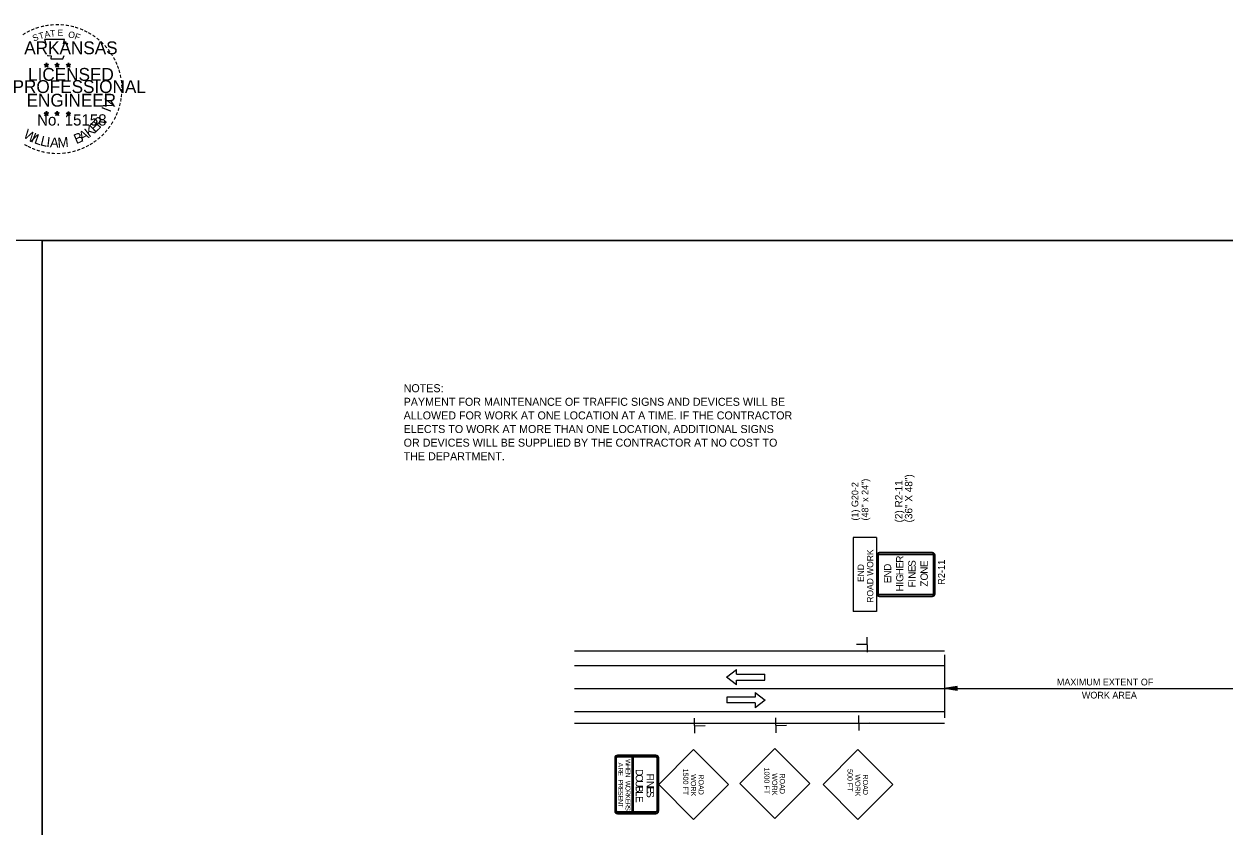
# Model space of a CAD drawing. Extents: x 32485 to 39285, y 55121 to 58033.
# Drawn here: x 37571 to 38508, y 57407 to 58033 of the extents above; entities that cross this region are included whole.
import ezdxf

# ---------------------------------------------------------------- set-up
doc = ezdxf.new("R2010")
doc.units = 0
for name, color, linetype in [('Default', 7, 'Continuous'), ('DSN_DRFT_Junk-No-Plot', 7, 'Continuous'), ('R_Border', 7, 'Continuous'), ('R_Border Notes', 7, 'Continuous'), ('R_Dimension', 7, 'Continuous'), ('R_Draft', 7, 'Continuous'), ('R_Exist Surface', 7, 'Continuous')]:
    doc.layers.add(name, color=color, linetype=linetype)

msp = doc.modelspace()

# ---------------------------------------------------------------- linework, layer by layer
at = {"layer": 'Default'}
for p, q in [((38236.12, 57618.46), (38236.12, 57588.47)), ((38236.71, 57618.46), (38236.71, 57588.47)), ((38237.54, 57588.47), (38237.54, 57618.46)), ((38279.66, 57620.6), (38238.26, 57620.6)), ((38279.66, 57620), (38238.26, 57620)), ((38238.26, 57619.17), (38279.66, 57619.17)), ((38280.37, 57618.46), (38280.37, 57588.47)), ((38281.21, 57588.47), (38281.21, 57618.46)), ((38281.8, 57588.47), (38281.8, 57618.46)), ((38279.66, 57587.76), (38238.26, 57587.76)), ((38238.26, 57586.93), (38279.66, 57586.93)), ((38238.26, 57586.33), (38279.66, 57586.33)), ((38289.12, 57540.69), (38289.12, 57491.65)), ((38119.1, 57523.38), (38126.88, 57529.38)), ((38126.88, 57517.38), (38119.1, 57523.38)), ((38126.88, 57525.63), (38126.88, 57529.38)), ((38126.88, 57525.63), (38148.95, 57525.63)), ((38126.88, 57521.13), (38148.95, 57521.13)), ((38126.88, 57517.38), (38126.88, 57521.13)), ((38148.95, 57521.13), (38148.95, 57525.63)), ((38141.33, 57511.53), (38141.33, 57507.78)), ((38141.33, 57511.53), (38149.11, 57505.53)), ((38289.12, 57514.51), (38546.87, 57514.51)), ((38345.15, 57514.51), (38490.85, 57514.51)), ((38141.33, 57507.78), (38119.26, 57507.78)), ((38119.26, 57507.78), (38119.26, 57503.28)), ((38141.33, 57503.28), (38119.26, 57503.28)), ((38149.11, 57505.53), (38141.33, 57499.53)), ((38141.33, 57503.28), (38141.33, 57499.53)), ((38031.84, 57460.42), (38031.84, 57419.02)), ((38032.43, 57460.42), (38032.43, 57419.02)), ((38033.26, 57419.02), (38033.26, 57460.42)), ((38063.96, 57462.57), (38033.98, 57462.57)), ((38063.96, 57461.97), (38033.98, 57461.97)), ((38033.98, 57461.14), (38063.96, 57461.14)), ((38045.46, 57418.31), (38045.46, 57461.14)), ((38045.46, 57461.14), (38046.29, 57461.14)), ((38046.29, 57461.14), (38046.29, 57418.31)), ((38064.67, 57460.42), (38064.67, 57419.02)), ((38065.5, 57419.02), (38065.5, 57460.42)), ((38066.1, 57419.02), (38066.1, 57460.42)), ((38063.96, 57418.31), (38033.98, 57418.31)), ((38033.98, 57417.48), (38063.96, 57417.48)), ((38046.29, 57418.31), (38045.46, 57418.31)), ((38033.98, 57416.88), (38063.96, 57416.88))]:
    msp.add_line(p, q, dxfattribs=at)
for points in [[(35885, 57863.91), (35885, 56763.91), (37585, 56763.91), (37585, 57863.91)], [(37585, 57863.91), (37585, 56763.91), (39285, 56763.91), (39285, 57863.91)]]:
    msp.add_lwpolyline(points, close=True, dxfattribs=at)
for centre, radius, start, end in [((38238.26, 57618.46), 2.14, 90, 180), ((38238.26, 57618.46), 1.55, 90, 180), ((38238.26, 57618.46), 0.714, 90, 180), ((38279.66, 57618.46), 2.14, 0.00001, 90.00001), ((38279.66, 57618.46), 1.55, 0, 90.00001), ((38279.66, 57618.46), 0.714, 0, 90.00001), ((38238.26, 57588.47), 2.14, 180, 270), ((38238.26, 57588.47), 1.55, 180, 270.00001), ((38238.26, 57588.47), 0.714, 180, 270.00001), ((38279.66, 57588.47), 2.14, 270, 0.00001), ((38279.66, 57588.47), 1.55, 270.00001, 0), ((38279.66, 57588.47), 0.714, 270.00001, 0), ((38033.98, 57460.42), 2.14, 90, 180.00001), ((38033.98, 57460.42), 1.55, 90.00001, 180), ((38033.98, 57460.42), 0.714, 90.00001, 180), ((38063.96, 57460.42), 2.14, 0, 90), ((38063.96, 57460.42), 1.55, 0, 90.00001), ((38063.96, 57460.42), 0.714, 0, 90.00001), ((38033.98, 57419.02), 2.14, 180.00001, 270.00001), ((38033.98, 57419.02), 1.55, 180, 270.00001), ((38033.98, 57419.02), 0.714, 180, 270.00001), ((38063.96, 57419.02), 2.14, 270, 0), ((38063.96, 57419.02), 1.55, 270, 0), ((38063.96, 57419.02), 0.714, 270, 0)]:
    msp.add_arc(centre, radius, start, end, dxfattribs=at)
at = {"layer": 'DSN_DRFT_Junk-No-Plot'}
msp.add_lwpolyline([(37585, 57863.91), (39285, 57863.91), (39285, 56763.91), (37585, 56763.91)], close=True, dxfattribs=at)
at = {"layer": 'R_Border'}
for p, q in [((38217.92, 57632.43), (38217.92, 57574.5)), ((38236.12, 57632.43), (38217.92, 57632.43)), ((38236.12, 57632.43), (38236.12, 57574.5)), ((38236.12, 57574.5), (38217.92, 57574.5)), ((38228.51, 57548.79), (38220.46, 57548.76)), ((38228.65, 57554.66), (38228.7, 57542.88)), ((38222.53, 57481.76), (38222.33, 57493.54)), ((38094.2, 57479.6), (38093.99, 57491.38)), ((38094.26, 57485.47), (38102.31, 57485.6)), ((38157.84, 57479.9), (38157.64, 57491.67)), ((38157.91, 57485.76), (38165.95, 57485.89)), ((38222.6, 57487.63), (38230.64, 57487.76)), ((38066.1, 57439.72), (38093.36, 57467)), ((38120.64, 57439.72), (38093.36, 57467)), ((38129.45, 57440.42), (38156.71, 57467.7)), ((38183.99, 57440.42), (38156.71, 57467.7)), ((38194.35, 57439.63), (38221.61, 57466.91)), ((38248.89, 57439.63), (38221.61, 57466.91)), ((38093.36, 57412.44), (38066.1, 57439.72)), ((38093.36, 57412.44), (38120.64, 57439.72)), ((38156.71, 57413.14), (38129.45, 57440.42)), ((38156.71, 57413.14), (38183.99, 57440.42)), ((38221.61, 57412.35), (38194.35, 57439.63)), ((38221.61, 57412.35), (38248.89, 57439.63))]:
    msp.add_line(p, q, dxfattribs=at)
at = {"layer": 'R_Border Notes'}
msp.add_lwpolyline([(35885, 56763.91), (37585, 56763.91), (37585, 57863.91), (35885, 57863.91)], close=True, dxfattribs=at)
at = {"layer": 'R_Dimension'}
for p, q in [((37586.59, 58001.4), (37588.33, 58000.85)), ((37586.59, 58001.4), (37587.85, 58001.18)), ((37586.59, 58001.4), (37587.77, 58000.79)), ((37587.25, 57999.36), (37588.33, 58000.85)), ((37587.25, 57999.36), (37587.88, 58000.58)), ((37587.25, 57999.36), (37588.32, 58000.45)), ((37588.33, 58002.67), (37588.13, 58001.41)), ((37589.4, 57999.36), (37588.32, 58000.43)), ((37588.33, 58000.85), (37588.33, 58002.67)), ((37588.33, 58002.67), (37588.58, 58001.42)), ((37590.07, 58001.4), (37588.33, 58000.85)), ((37589.4, 57999.36), (37588.33, 58000.85)), ((37590.07, 58001.4), (37588.64, 58001.16)), ((37589.4, 57999.36), (37588.71, 58000.82)), ((37590.07, 58001.4), (37589.05, 58000.89)), ((37594.94, 58001.4), (37596.68, 58000.85)), ((37594.94, 58001.4), (37596.2, 58001.18)), ((37594.94, 58001.4), (37596.12, 58000.79)), ((37595.6, 57999.36), (37596.68, 58000.85)), ((37595.6, 57999.36), (37596.23, 58000.58)), ((37595.6, 57999.36), (37596.67, 58000.45)), ((37596.68, 58002.67), (37596.48, 58001.41)), ((37597.75, 57999.36), (37596.67, 58000.43)), ((37596.68, 58000.85), (37596.68, 58002.67)), ((37596.68, 58002.67), (37596.93, 58001.42)), ((37598.42, 58001.4), (37596.68, 58000.85)), ((37597.75, 57999.36), (37596.68, 58000.85)), ((37598.42, 58001.4), (37596.99, 58001.16)), ((37597.75, 57999.36), (37597.06, 58000.82)), ((37598.42, 58001.4), (37597.4, 58000.89)), ((37603.76, 58001.34), (37605.5, 58000.79)), ((37603.76, 58001.34), (37605.02, 58001.12)), ((37603.76, 58001.34), (37604.94, 58000.73)), ((37604.42, 57999.3), (37605.5, 58000.79)), ((37604.42, 57999.3), (37605.05, 58000.52)), ((37604.42, 57999.3), (37605.49, 58000.39)), ((37605.5, 58002.61), (37605.3, 58001.35)), ((37606.57, 57999.3), (37605.49, 58000.37)), ((37605.5, 58000.79), (37605.5, 58002.61)), ((37605.5, 58002.61), (37605.75, 58001.36)), ((37607.24, 58001.34), (37605.5, 58000.79)), ((37606.57, 57999.3), (37605.5, 58000.79)), ((37607.24, 58001.34), (37605.81, 58001.1)), ((37606.57, 57999.3), (37605.88, 58000.76)), ((37607.24, 58001.34), (37606.22, 58000.83)), ((37586.57, 57963.54), (37588.31, 57962.98)), ((37586.57, 57963.54), (37587.83, 57963.31)), ((37586.57, 57963.54), (37587.75, 57962.93)), ((37587.23, 57961.5), (37588.31, 57962.98)), ((37587.23, 57961.5), (37587.86, 57962.72)), ((37587.23, 57961.5), (37588.3, 57962.58)), ((37588.31, 57964.81), (37588.11, 57963.55)), ((37589.38, 57961.5), (37588.3, 57962.57)), ((37588.31, 57962.98), (37588.31, 57964.81)), ((37588.31, 57964.81), (37588.56, 57963.56)), ((37590.05, 57963.54), (37588.31, 57962.98)), ((37589.38, 57961.5), (37588.31, 57962.98)), ((37590.05, 57963.54), (37588.62, 57963.29)), ((37589.38, 57961.5), (37588.69, 57962.95)), ((37590.05, 57963.54), (37589.03, 57963.03)), ((37594.91, 57963.54), (37596.66, 57962.98)), ((37594.91, 57963.54), (37596.18, 57963.31)), ((37594.91, 57963.54), (37596.1, 57962.93)), ((37595.58, 57961.5), (37596.66, 57962.98)), ((37595.58, 57961.5), (37596.21, 57962.72)), ((37595.58, 57961.5), (37596.65, 57962.58)), ((37596.66, 57964.81), (37596.45, 57963.55)), ((37597.72, 57961.5), (37596.65, 57962.57)), ((37596.66, 57962.98), (37596.66, 57964.81)), ((37596.66, 57964.81), (37596.9, 57963.56)), ((37598.39, 57963.54), (37596.66, 57962.98)), ((37597.72, 57961.5), (37596.66, 57962.98)), ((37598.39, 57963.54), (37596.96, 57963.29)), ((37597.72, 57961.5), (37597.04, 57962.95)), ((37598.39, 57963.54), (37597.37, 57963.03)), ((37603.75, 57963.49), (37605.49, 57962.93)), ((37603.75, 57963.49), (37605.01, 57963.26)), ((37603.75, 57963.49), (37604.93, 57962.88)), ((37604.41, 57961.45), (37605.49, 57962.93)), ((37604.41, 57961.45), (37605.04, 57962.67)), ((37604.41, 57961.45), (37605.48, 57962.53)), ((37605.49, 57964.76), (37605.29, 57963.5)), ((37606.56, 57961.45), (37605.48, 57962.52)), ((37605.49, 57962.93), (37605.49, 57964.76)), ((37605.49, 57964.76), (37605.74, 57963.51)), ((37607.23, 57963.49), (37605.49, 57962.93)), ((37606.56, 57961.45), (37605.49, 57962.93)), ((37607.23, 57963.49), (37605.8, 57963.24)), ((37606.56, 57961.45), (37605.87, 57962.9)), ((37607.23, 57963.49), (37606.21, 57962.98))]:
    msp.add_line(p, q, dxfattribs=at)
for points in [[(37586.79, 58020.79), (37588.14, 58016.66)], [(37604.35, 58016.18), (37605.06, 58017.6), (37601.63, 58017.48), (37602.37, 58020.79), (37586.79, 58020.79)], [(37589.25, 58008.68), (37589.25, 58008.24), (37592.07, 58008.15), (37591.8, 58005.78), (37601.15, 58005.78), (37602.15, 58008.46)], [(37588.33, 58002.67), (37589.4, 57999.36), (37586.59, 58001.4), (37590.07, 58001.4), (37587.25, 57999.36), (37588.33, 58002.67)], [(37596.68, 58002.67), (37597.75, 57999.36), (37594.94, 58001.4), (37598.42, 58001.4), (37595.6, 57999.36), (37596.68, 58002.67)], [(37605.5, 58002.61), (37606.57, 57999.3), (37603.76, 58001.34), (37607.24, 58001.34), (37604.42, 57999.3), (37605.5, 58002.61)], [(37588.31, 57964.81), (37589.38, 57961.5), (37586.57, 57963.54), (37590.05, 57963.54), (37587.23, 57961.5), (37588.31, 57964.81)], [(37596.66, 57964.81), (37597.72, 57961.5), (37594.91, 57963.54), (37598.39, 57963.54), (37595.58, 57961.5), (37596.66, 57964.81)], [(37605.49, 57964.76), (37606.56, 57961.45), (37603.75, 57963.49), (37607.23, 57963.49), (37604.41, 57961.45), (37605.49, 57964.76)]]:
    msp.add_lwpolyline(points, dxfattribs=at)
for centre, radius in [((37588.33, 58000.84), 0.861), ((37588.33, 58000.84), 0.723), ((37588.33, 58000.84), 0.579), ((37588.33, 58000.84), 0.495), ((37588.33, 58000.84), 0.374), ((37588.33, 58000.84), 0.248), ((37588.33, 58000.84), 0.148), ((37596.68, 58000.84), 0.861), ((37596.68, 58000.84), 0.723), ((37596.68, 58000.84), 0.579), ((37596.68, 58000.84), 0.495), ((37596.68, 58000.84), 0.374), ((37596.68, 58000.84), 0.248), ((37596.68, 58000.84), 0.148), ((37605.5, 58000.78), 0.861), ((37605.5, 58000.78), 0.723), ((37605.5, 58000.78), 0.579), ((37605.5, 58000.78), 0.495), ((37605.5, 58000.78), 0.374), ((37605.5, 58000.78), 0.248), ((37605.5, 58000.78), 0.148), ((37588.31, 57962.98), 0.861), ((37588.31, 57962.98), 0.723), ((37588.31, 57962.98), 0.579), ((37588.31, 57962.98), 0.495), ((37588.31, 57962.98), 0.374), ((37588.31, 57962.98), 0.248), ((37588.31, 57962.98), 0.148), ((37596.65, 57962.98), 0.861), ((37596.65, 57962.98), 0.723), ((37596.65, 57962.98), 0.579), ((37596.65, 57962.98), 0.495), ((37596.65, 57962.98), 0.374), ((37596.65, 57962.98), 0.248), ((37596.65, 57962.98), 0.148), ((37605.49, 57962.93), 0.861), ((37605.49, 57962.93), 0.723), ((37605.49, 57962.93), 0.579), ((37605.49, 57962.93), 0.495), ((37605.49, 57962.93), 0.374), ((37605.49, 57962.93), 0.248), ((37605.49, 57962.93), 0.148)]:
    msp.add_circle(centre, radius, dxfattribs=at)
at = {"layer": 'R_Draft'}
for p, q in [((38299.12, 57516.01), (38289.12, 57514.51)), ((38299.12, 57513.01), (38289.12, 57514.51)), ((38299.12, 57515.76), (38290.79, 57514.51)), ((38299.12, 57513.26), (38290.79, 57514.51)), ((38299.12, 57515.5), (38292.51, 57514.51)), ((38299.12, 57513.51), (38292.51, 57514.51)), ((38299.12, 57515.25), (38294.18, 57514.51)), ((38299.12, 57513.76), (38294.18, 57514.51)), ((38299.12, 57515), (38295.87, 57514.51)), ((38299.12, 57514.02), (38295.87, 57514.51)), ((38299.12, 57514.74), (38297.54, 57514.51)), ((38299.12, 57514.27), (38297.54, 57514.51)), ((38299.12, 57513.01), (38299.12, 57516.01))]:
    msp.add_line(p, q, dxfattribs=at)
at = {"layer": 'R_Exist Surface'}
for p, q in [((38000.34, 57544.01), (38289.12, 57544.01)), ((38000.34, 57532.51), (38289.12, 57532.51)), ((38000.34, 57514.51), (38289.12, 57514.51)), ((38000.34, 57496.51), (38289.12, 57496.51)), ((38000.34, 57487.51), (38289.12, 57487.51))]:
    msp.add_line(p, q, dxfattribs=at)

# ---------------------------------------------------------------- texts
at = {"layer": 'Default'}
for s, height, p in [('NOTES: ', 6.25, (37867.1, 57745.7)), ('PAYMENT FOR MAINTENANCE OF TRAFFIC SIGNS AND DEVICES WILL BE ', 6.25, (37867.1, 57735.08)), ('ALLOWED FOR WORK AT ONE LOCATION AT A TIME. IF THE CONTRACTOR', 6.25, (37867.1, 57724.46)), ('ELECTS TO WORK AT MORE THAN ONE LOCATION, ADDITIONAL SIGNS', 6.25, (37867.1, 57713.83)), ('OR DEVICES WILL BE SUPPLIED BY THE CONTRACTOR AT NO COST TO ', 6.25, (37867.1, 57703.21)), ('THE DEPARTMENT.', 6.25, (37867.1, 57692.58)), ('MAXIMUM EXTENT OF ', 5.25, (38376.8, 57516.94)), ('WORK AREA', 5.25, (38396.32, 57506.75))]:
    msp.add_text(s, height=height, dxfattribs=at).set_placement(p)
for s, height, rotation, p in [('R', 5.71, 90, (38257.06, 57612.7)), ('S', 5.71, 90, (38266.57, 57609.55)), ('R2-11', 5.384, 90, (38289.42, 57595.41)), ('D', 5.71, 90, (38247.54, 57606.41)), ('N', 5.71, 90, (38247.54, 57601.15)), ('E', 5.71, 90, (38257.06, 57608.18)), ('H', 5.71, 90, (38257.06, 57602.92)), ('E', 5.71, 90, (38266.57, 57605.44)), ('N', 5.71, 90, (38266.57, 57600.18)), ('E', 5.71, 90, (38276.09, 57609.35)), ('N', 5.71, 90, (38276.09, 57604.09)), ('E', 5.71, 90, (38247.54, 57596.64)), ('G', 5.71, 90, (38257.06, 57597.78)), ('I', 5.71, 90, (38257.06, 57595.61)), ('I', 5.71, 90, (38266.57, 57597.89)), ('F', 5.71, 90, (38266.57, 57593.49)), ('O', 5.71, 90, (38276.09, 57598.78)), ('Z', 5.71, 90, (38276.09, 57594.04)), ('H', 5.71, 90, (38257.06, 57590.35)), ('A', 3.81, 270, (38034.51, 57456.78)), ('W', 3.81, 270, (38040.22, 57459.42)), ('H', 3.81, 270, (38040.22, 57455.46)), ('R', 3.81, 270, (38034.51, 57452.97)), ('E', 3.81, 270, (38034.51, 57449.74)), ('E', 3.81, 270, (38040.22, 57451.96)), ('N', 3.81, 270, (38040.22, 57448.95)), ('O', 5.71, 270, (38048.19, 57447.49)), ('D', 5.71, 270, (38048.19, 57451.72)), ('F', 5.71, 270, (38056.76, 57448.23)), ('P', 3.81, 270, (38034.51, 57443.57)), ('R', 3.81, 270, (38034.51, 57440.41)), ('E', 3.81, 270, (38034.51, 57437.17)), ('O', 3.81, 270, (38040.22, 57438.68)), ('W', 3.81, 270, (38040.22, 57442.56)), ('U', 5.71, 270, (38048.19, 57442.98)), ('B', 5.71, 270, (38048.19, 57438.52)), ('I', 5.71, 270, (38056.76, 57444.52)), ('N', 5.71, 270, (38056.76, 57442.46)), ('E', 5.71, 270, (38056.76, 57438.01)), ('S', 3.81, 270, (38034.51, 57434.43)), ('E', 3.81, 270, (38034.51, 57431.2)), ('N', 3.81, 270, (38034.51, 57428.19)), ('R', 3.81, 270, (38040.22, 57435.14)), ('K', 3.81, 270, (38040.22, 57431.9)), ('E', 3.81, 270, (38040.22, 57428.59)), ('L', 5.71, 270, (38048.19, 57434.35)), ('E', 5.71, 270, (38048.19, 57430.64)), ('S', 5.71, 270, (38056.76, 57434.41)), ('T', 3.81, 270, (38034.51, 57425.03)), ('S', 3.81, 270, (38040.22, 57422.61)), ('R', 3.81, 270, (38040.22, 57425.58))]:
    msp.add_text(s, height=height, rotation=rotation, dxfattribs=at).set_placement(p)
at = {"layer": 'R_Border'}
for s, height, rotation, p in [('(1) G20-2', 5.234, 90, (38221.86, 57645.59)), ('(48" x 24")', 5.2332, 90, (38229.71, 57645.59)), ('ROAD WORK', 4.946, 90, (38233.55, 57581.51)), ('END', 4.946, 90, (38226.25, 57597.65)), ('1500 FT', 4.019, 270.00057, (38085.18, 57452.02)), ('WORK', 4.018, 270.00004, (38091.22, 57447.68)), ('ROAD', 4.019, 270.00045, (38097.25, 57447.6)), ('1000 FT', 4.019, 270.00057, (38148.54, 57452.87)), ('WORK', 4.018, 270.00004, (38154.57, 57448.38)), ('ROAD', 4.019, 270.00045, (38160.6, 57448.3)), (' 500 FT', 4.019, 270.00057, (38213.44, 57453.27)), ('WORK', 4.018, 270.00004, (38219.47, 57447.59)), ('ROAD', 4.019, 270.00045, (38225.5, 57447.51))]:
    msp.add_text(s, height=height, rotation=rotation, dxfattribs=at).set_placement(p)
at = {"layer": 'R_Dimension'}
for s, height, rotation, p in [('-', 8, 28.79182, (37574.2, 58023.5)), ('-', 8, 24.30721, (37577.36, 58025.08)), ('-', 8, 19.17608, (37580.53, 58026.43)), ('T', 5, 16.4036, (37583.14, 58020.84)), ('-', 8, 13.63015, (37584.28, 58027.63)), ('A', 5, 11.21318, (37587.27, 58022.09)), ('-', 8, 10.21935, (37587.67, 58028.44)), ('T', 5, 6.02276, (37591.51, 58022.92)), ('-', 8, 5.89682, (37591.32, 58028.99)), ('-', 8, 0.18623, (37595.18, 58029.35)), ('E', 5, 0.83234, (37597.04, 58023.47)), ('-', 8, 357.74304, (37598.79, 58029.29)), ('-', 8, 352.16172, (37602.51, 58029.01)), ('O', 5, 350.4515, (37605.06, 58022.42)), ('-', 8, 347.20489, (37606.11, 58028.44)), ('-', 8, 342.3362, (37609.28, 58027.66)), ('-', 8, 337.85509, (37612.96, 58026.55)), ('-', 8, 334.12109, (37616.11, 58025.19)), ('-', 8, 329.64089, (37619.01, 58023.78)), ('-', 8, 34.06357, (37571.21, 58021.65)), ('S', 5, 21.59401, (37578.57, 58019.18)), ('F', 5, 340.07066, (37609.83, 58021.28)), ('-', 8, 325.86266, (37622.22, 58021.97)), ('-', 8, 320.52971, (37625.27, 58019.84)), ('-', 8, 315.57859, (37628.27, 58017.4)), ('-', 8, 309.87973, (37631.11, 58014.65)), ('-', 8, 306.65218, (37633.74, 58011.64)), ('-', 7, 303.67529, (37636.17, 58008.8)), ('-', 8, 299.66835, (37637.76, 58005.77)), ('-', 8, 294.66279, (37639.38, 58002.71)), ('-', 8, 290.57283, (37640.67, 57999.82)), ('-', 8, 285.12326, (37641.84, 57996.92)), ('-', 8, 280.54934, (37642.84, 57993.21)), ('-', 8, 276.59616, (37643.65, 57989.37)), ('-', 8, 274.33011, (37643.95, 57985.76)), ('-', 8, 269.94067, (37644.12, 57982.6)), ('V', 7.7, 72.65729, (37639.34, 57966.3)), ('-', 8, 255.7626, (37643.12, 57972.61)), ('-', 8, 260.99529, (37643.67, 57976)), ('-', 8, 263.5172, (37644.02, 57979.27)), ('I', 7.7, 69.03009, (37638.23, 57963.6)), ('-', 8, 244.61971, (37639.79, 57962.5)), ('-', 8, 247.88866, (37641.1, 57965.65)), ('-', 8, 252.86809, (37642.21, 57969.01)), ('K', 7.7, 36.91429, (37621.76, 57944.17)), ('E', 7.7, 44.01755, (37626.31, 57947.62)), ('R', 7.7, 50.36514, (37629.98, 57951.16)), (',', 7.7, 57.4684, (37633.59, 57955.57)), ('-', 8, 233.84524, (37635.81, 57955.48)), ('-', 8, 239.07125, (37637.82, 57958.74)), ('W', 7.7, 328.07311, (37569.71, 57944.85)), ('I', 7.7, 336.6877, (37575.65, 57941.3)), ('L', 7.7, 340.3149, (37578.3, 57940.08)), ('L', 7.7, 346.66249, (37583.1, 57938.36)), ('I', 7.7, 353.01009, (37588.06, 57937.18)), ('A', 7.7, 356.63729, (37590.94, 57936.75)), ('M', 7.7, 4.64735, (37597.36, 57936.46)), ('B', 7.7, 22.8589, (37611.69, 57939.12)), ('A', 7.7, 28.90423, (37616.18, 57940.99)), ('-', 8, 215.73633, (37625.91, 57944.92)), ('-', 8, 221.08509, (37628.65, 57947.28)), ('-', 8, 225.76533, (37631.26, 57949.83)), ('-', 8, 231.25377, (37633.66, 57952.65)), ('-', 8, 151.57039, (37575.42, 57940.16)), ('-', 8, 154.60019, (37578.03, 57938.93)), ('-', 8, 158.56121, (37581.15, 57937.66)), ('-', 8, 162.79826, (37584.58, 57936.59)), ('-', 8, 167.55551, (37588.16, 57935.77)), ('-', 8, 173.11546, (37592.02, 57935.22)), ('-', 8, 191.28576, (37607.2, 57936.09)), ('-', 8, 195.47429, (37610.85, 57937.09)), ('-', 8, 199.46435, (37614.17, 57938.27)), ('-', 8, 204.25161, (37617.33, 57939.66)), ('-', 8, 207.35684, (37620.45, 57941.26)), ('-', 8, 212.24909, (37623.24, 57942.99)), ('-', 8, 176.51827, (37595.76, 57934.96)), ('-', 8, 181.59176, (37599.48, 57935.05)), ('-', 8, 185.81666, (37603.52, 57935.43))]:
    msp.add_text(s, height=height, rotation=rotation, dxfattribs=at).set_placement(p)
for s, height, p in [('ARKANSAS', 10, (37571.06, 58009.35)), ('LICENSED', 10, (37574.04, 57988.61)), ('PROFESSIONAL', 10, (37561.93, 57979.09)), ('ENGINEER', 10, (37572.86, 57968.46)), ('No. 15158', 8.785, (37581.07, 57953.71)), ('AAMU', 0.0001, (37596.33, 57936.44))]:
    msp.add_text(s, height=height, dxfattribs=at).set_placement(p)
at = {"layer": 'R_Draft'}
for s, height, p in [('(36" X 48")', 5.8301, (38264.06, 57644.08)), ('(2) R2-11', 5.83, (38256.34, 57644.08))]:
    msp.add_text(s, height=height, rotation=90, dxfattribs=at).set_placement(p)

doc.saveas('drawing.dxf')
